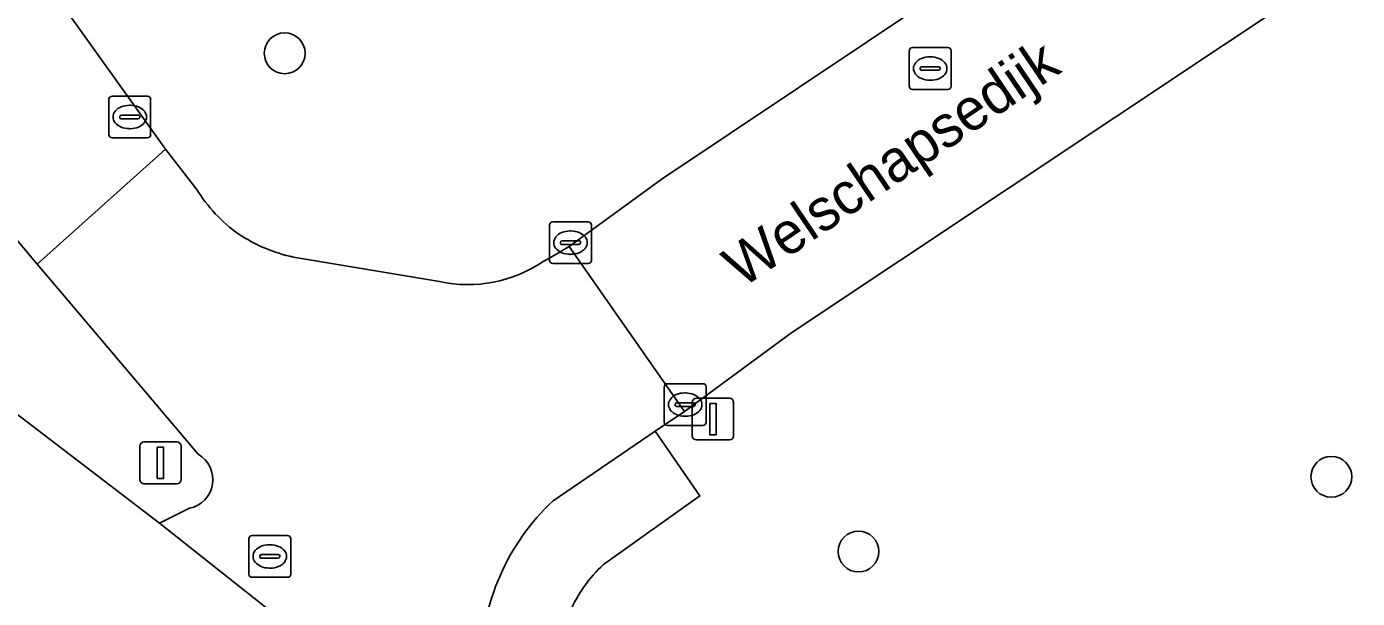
# Model space of a CAD drawing. Extents: x 157445 to 158888, y 383061 to 384688.
# Drawn here: x 157857.9 to 157889.8, y 383617.35 to 383631.04 of the extents above; entities that cross this region are included whole.
import ezdxf

# ---------------------------------------------------------------- set-up
doc = ezdxf.new("R2010")
doc.units = 0
for name, color, linetype in [('IMGEO_Boom', 7, 'Continuous'), ('IMGEO_Brandkraan', 7, 'Continuous'), ('IMGEO_Erf', 7, 'Continuous'), ('IMGEO_Fietspad_open', 7, 'Continuous'), ('IMGEO_Groenvoorziening', 7, 'Continuous'), ('IMGEO_Kolk', 7, 'Continuous'), ('IMGEO_Lichtmast', 7, 'Continuous'), ('IMGEO_Openbare_ruimte_label', 7, 'Continuous'), ('IMGEO_Rijbaan_lokaal_gesloten', 7, 'Continuous'), ('IMGEO_Rijbaan_lokaal_open', 7, 'Continuous'), ('IMGEO_Rioolput', 7, 'Continuous'), ('IMGEO_Verkeersbordpaal', 7, 'Continuous'), ('IMGEO_Voetpad_open', 7, 'Continuous')]:
    doc.layers.add(name, color=color, linetype=linetype)

msp = doc.modelspace()

# ---------------------------------------------------------------- linework, layer by layer
at = {"layer": 'IMGEO_Boom'}
for centre in [(157864.084, 383630.402), (157889.178, 383620.258), (157877.841, 383618.467)]:
    msp.add_circle(centre, 0.489, dxfattribs=at)
at = {"layer": 'IMGEO_Brandkraan'}
for p, q in [((157879.134, 383630.537), (157879.986, 383630.537)), ((157879.059, 383629.611), (157879.059, 383630.463)), ((157879.547, 383630.317), (157879.572, 383630.317)), ((157880.06, 383630.463), (157880.06, 383629.611)), ((157879.318, 383630.031), (157879.318, 383630.043)), ((157879.756, 383629.994), (157879.358, 383629.994)), ((157879.361, 383630.08), (157879.759, 383630.08)), ((157879.802, 383630.043), (157879.802, 383630.031)), ((157879.57, 383629.757), (157879.545, 383629.757)), ((157879.986, 383629.537), (157879.134, 383629.537))]:
    msp.add_line(p, q, dxfattribs=at)
for points in [[(157879.134, 383630.537), (157879.986, 383630.537)], [(157879.059, 383629.611), (157879.059, 383630.463)], [(157880.06, 383630.463), (157880.06, 383629.611)], [(157879.986, 383629.537), (157879.134, 383629.537)]]:
    msp.add_lwpolyline(points, dxfattribs=at)
for centre, radius, start, end in [((157879.136, 383630.461), 0.0765, 91.552, 178.448), ((157879.136, 383630.461), 0.0765, 91.552, 178.448), ((157879.984, 383630.461), 0.0765, 1.552, 88.448), ((157879.984, 383630.461), 0.0765, 1.552, 88.448), ((157879.358, 383630.04), 0.0403, 85.8775, 175.7526), ((157879.355, 383630.03), 0.0366, 178.938, 274.7102), ((157879.759, 383630.037), 0.043, 264.8664, 352.4533), ((157879.763, 383630.042), 0.0386, 1.7309, 96.639), ((157879.136, 383629.613), 0.0765, 181.552, 268.448), ((157879.136, 383629.613), 0.0765, 181.552, 268.448), ((157879.984, 383629.613), 0.0765, 271.552, 358.448), ((157879.984, 383629.613), 0.0765, 271.552, 358.448)]:
    msp.add_arc(centre, radius, start, end, dxfattribs=at)
for centre, major_axis, ratio, start_param, end_param in [((157879.546, 383630.037), (-0.387, 0.002), 0.722429, 4.712389, 7.853982), ((157879.571, 383630.037), (-0.39, 0.002), 0.717154, 1.570796, 4.712389)]:
    msp.add_ellipse(centre, major_axis=major_axis, ratio=ratio, start_param=start_param, end_param=end_param, dxfattribs=at)
at = {"layer": 'IMGEO_Erf'}
for points in [[(157898.785, 383680.85), (157847.632, 383646.169), (157853.571, 383638.788), (157861.226, 383628.104), (157861.967, 383627.151)], [(157870.28, 383625.415), (157870.471, 383625.516), (157870.906, 383625.776), (157873.135, 383627.394), (157904.332, 383648.231)], [(157864.294, 383625.52), (157867.796, 383624.934)]]:
    msp.add_lwpolyline(points, dxfattribs=at)
for centre, radius, start, end in [((157865.117, 383629.096), 3.702, 211.6974, 234.8047), ((157865.049, 383629.151), 3.708, 236.1489, 258.2581), ((157868.478, 383628.067), 3.206, 257.7179, 304.2003)]:
    msp.add_arc(centre, radius, start, end, dxfattribs=at)
at = {"layer": 'IMGEO_Fietspad_open'}
msp.add_lwpolyline([(157853.571, 383638.788), (157849.584, 383635.58), (157858.15, 383625.351), (157861.226, 383628.104)], close=True, dxfattribs=at)
at = {"layer": 'IMGEO_Groenvoorziening'}
for points in [[(157904.285, 383642.613), (157897.583, 383637.97), (157896.712, 383637.403), (157899.26, 383633.792), (157895.94, 383631.526), (157893.402, 383635.177), (157891.801, 383634.068), (157876.245, 383623.717), (157873.672, 383621.824), (157872.964, 383621.347), (157874.037, 383619.798), (157871.729, 383618.155)], [(157862.01, 383620.797), (157858.877, 383624.494), (157858.15, 383625.351), (157849.584, 383635.58)], [(157852.753, 383625.437), (157856.142, 383622.915), (157861.08, 383619.146), (157861.8, 383619.502)]]:
    msp.add_lwpolyline(points, dxfattribs=at)
for centre, radius, start, end in [((157861.663, 383620.189), 0.7, 281.3171, 60.2608), ((157873.934, 383615.734), 3.275, 132.3217, 156.9275)]:
    msp.add_arc(centre, radius, start, end, dxfattribs=at)
at = {"layer": 'IMGEO_Kolk'}
for p, q in [((157859.869, 383628.45), (157859.869, 383629.302)), ((157859.944, 383629.376), (157860.796, 383629.376)), ((157860.87, 383629.302), (157860.87, 383628.45)), ((157860.171, 383628.919), (157860.569, 383628.919)), ((157860.357, 383629.156), (157860.382, 383629.156)), ((157860.128, 383628.87), (157860.128, 383628.882)), ((157860.566, 383628.833), (157860.168, 383628.833)), ((157860.612, 383628.882), (157860.612, 383628.87)), ((157860.796, 383628.376), (157859.944, 383628.376)), ((157860.38, 383628.596), (157860.355, 383628.596)), ((157870.435, 383625.44), (157870.435, 383626.292)), ((157870.51, 383626.366), (157871.362, 383626.366)), ((157870.923, 383626.146), (157870.948, 383626.146)), ((157871.436, 383626.292), (157871.436, 383625.44)), ((157870.694, 383625.86), (157870.694, 383625.872)), ((157871.132, 383625.823), (157870.734, 383625.823)), ((157870.737, 383625.909), (157871.135, 383625.909)), ((157871.178, 383625.872), (157871.178, 383625.86)), ((157870.946, 383625.586), (157870.921, 383625.586)), ((157871.362, 383625.366), (157870.51, 383625.366)), ((157873.185, 383621.561), (157873.185, 383622.413)), ((157873.26, 383622.487), (157874.112, 383622.487)), ((157873.673, 383622.267), (157873.698, 383622.267)), ((157874.186, 383622.413), (157874.186, 383621.561)), ((157873.444, 383621.981), (157873.444, 383621.993)), ((157873.882, 383621.944), (157873.484, 383621.944)), ((157873.487, 383622.03), (157873.885, 383622.03)), ((157873.928, 383621.993), (157873.928, 383621.981)), ((157873.696, 383621.707), (157873.671, 383621.707)), ((157874.112, 383621.487), (157873.26, 383621.487))]:
    msp.add_line(p, q, dxfattribs=at)
for points in [[(157859.869, 383628.45), (157859.869, 383629.302)], [(157859.944, 383629.376), (157860.796, 383629.376)], [(157860.87, 383629.302), (157860.87, 383628.45)], [(157860.796, 383628.376), (157859.944, 383628.376)], [(157870.435, 383625.44), (157870.435, 383626.292)], [(157870.51, 383626.366), (157871.362, 383626.366)], [(157871.436, 383626.292), (157871.436, 383625.44)], [(157871.362, 383625.366), (157870.51, 383625.366)], [(157873.185, 383621.561), (157873.185, 383622.413)], [(157873.26, 383622.487), (157874.112, 383622.487)], [(157874.186, 383622.413), (157874.186, 383621.561)], [(157874.112, 383621.487), (157873.26, 383621.487)]]:
    msp.add_lwpolyline(points, dxfattribs=at)
for centre, radius, start, end in [((157859.946, 383629.3), 0.0765, 91.552, 178.448), ((157859.946, 383629.3), 0.0765, 91.552, 178.448), ((157860.794, 383629.3), 0.0765, 1.552, 88.448), ((157860.794, 383629.3), 0.0765, 1.552, 88.448), ((157860.168, 383628.879), 0.0403, 85.8775, 175.7526), ((157860.573, 383628.881), 0.0386, 1.7309, 96.639), ((157860.165, 383628.869), 0.0366, 178.938, 274.7102), ((157860.569, 383628.876), 0.043, 264.8664, 352.4533), ((157859.946, 383628.452), 0.0765, 181.552, 268.448), ((157859.946, 383628.452), 0.0765, 181.552, 268.448), ((157860.794, 383628.452), 0.0765, 271.552, 358.448), ((157860.794, 383628.452), 0.0765, 271.552, 358.448), ((157870.512, 383626.29), 0.0765, 91.552, 178.448), ((157870.512, 383626.29), 0.0765, 91.552, 178.448), ((157871.36, 383626.29), 0.0765, 1.552, 88.448), ((157871.36, 383626.29), 0.0765, 1.552, 88.448), ((157870.734, 383625.869), 0.0403, 85.8775, 175.7526), ((157870.731, 383625.859), 0.0366, 178.938, 274.7102), ((157871.135, 383625.866), 0.043, 264.8664, 352.4533), ((157871.139, 383625.871), 0.0386, 1.7309, 96.639), ((157870.512, 383625.442), 0.0765, 181.552, 268.448), ((157870.512, 383625.442), 0.0765, 181.552, 268.448), ((157871.36, 383625.442), 0.0765, 271.552, 358.448), ((157871.36, 383625.442), 0.0765, 271.552, 358.448), ((157873.262, 383622.411), 0.0765, 91.552, 178.448), ((157873.262, 383622.411), 0.0765, 91.552, 178.448), ((157874.11, 383622.411), 0.0765, 1.552, 88.448), ((157874.11, 383622.411), 0.0765, 1.552, 88.448), ((157873.484, 383621.99), 0.0403, 85.8775, 175.7526), ((157873.481, 383621.98), 0.0366, 178.938, 274.7102), ((157873.885, 383621.987), 0.043, 264.8664, 352.4533), ((157873.889, 383621.992), 0.0386, 1.7309, 96.639), ((157873.262, 383621.563), 0.0765, 181.552, 268.448), ((157873.262, 383621.563), 0.0765, 181.552, 268.448), ((157874.11, 383621.563), 0.0765, 271.552, 358.448), ((157874.11, 383621.563), 0.0765, 271.552, 358.448)]:
    msp.add_arc(centre, radius, start, end, dxfattribs=at)
for centre, major_axis, ratio, start_param, end_param in [((157860.356, 383628.876), (-0.387, 0.002), 0.722429, 4.712389, 7.853982), ((157860.381, 383628.876), (-0.39, 0.002), 0.717154, 1.570796, 4.712389), ((157870.922, 383625.866), (-0.387, 0.002), 0.722429, 4.712389, 7.853982), ((157870.947, 383625.866), (-0.39, 0.002), 0.717154, 1.570796, 4.712389), ((157873.672, 383621.987), (-0.387, 0.002), 0.722429, 4.712389, 7.853982), ((157873.697, 383621.987), (-0.39, 0.002), 0.717154, 1.570796, 4.712389)]:
    msp.add_ellipse(centre, major_axis=major_axis, ratio=ratio, start_param=start_param, end_param=end_param, dxfattribs=at)
at = {"layer": 'IMGEO_Lichtmast'}
for p, q in [((157873.856, 383621.239), (157873.856, 383622.039)), ((157873.856, 383622.039), (157873.856, 383621.239)), ((157873.956, 383622.139), (157874.746, 383622.139)), ((157874.746, 383622.139), (157873.956, 383622.139)), ((157874.846, 383622.039), (157874.846, 383621.239)), ((157874.846, 383621.239), (157874.846, 383622.039)), ((157874.746, 383621.139), (157873.956, 383621.139)), ((157873.956, 383621.139), (157874.746, 383621.139))]:
    msp.add_line(p, q, dxfattribs=at)
msp.add_lwpolyline([(157874.276, 383622.014), (157874.426, 383622.014), (157874.426, 383621.264), (157874.276, 383621.264), (157874.276, 383622.014)], dxfattribs=at)
for centre, start, end in [((157873.956, 383622.039), 90, 180), ((157873.956, 383622.039), 90, 180), ((157874.746, 383622.039), 0, 90), ((157874.746, 383622.039), 360, 90), ((157873.956, 383621.239), 180, 270), ((157873.956, 383621.239), 180, 270), ((157874.746, 383621.239), 270, 0), ((157874.746, 383621.239), 270, 0)]:
    msp.add_arc(centre, 0.1, start, end, dxfattribs=at)
at = {"layer": 'IMGEO_Rijbaan_lokaal_gesloten'}
msp.add_lwpolyline([(157881.641, 383602.379), (157870.429, 383611.742), (157861.08, 383619.146), (157856.142, 383622.915), (157852.589, 383618.202), (157856.906, 383614.859), (157858.634, 383613.533)], dxfattribs=at)
at = {"layer": 'IMGEO_Rijbaan_lokaal_open'}
for points in [[(157904.332, 383648.231), (157873.135, 383627.394), (157870.906, 383625.776), (157873.672, 383621.824), (157876.245, 383623.717), (157891.801, 383634.068), (157893.402, 383635.177), (157896.712, 383637.403), (157897.583, 383637.97), (157904.285, 383642.613)], [(157861.967, 383627.151), (157861.226, 383628.104), (157858.15, 383625.351), (157858.877, 383624.494), (157862.01, 383620.797)], [(157870.517, 383619.684), (157872.964, 383621.347), (157873.672, 383621.824), (157870.906, 383625.776), (157870.471, 383625.516), (157870.28, 383625.415)], [(157867.796, 383624.934), (157864.294, 383625.52)], [(157861.8, 383619.502), (157861.08, 383619.146), (157870.429, 383611.742)]]:
    msp.add_lwpolyline(points, dxfattribs=at)
for centre, radius, start, end in [((157865.117, 383629.096), 3.702, 211.6974, 234.8047), ((157865.049, 383629.151), 3.708, 236.1489, 258.2581), ((157868.478, 383628.067), 3.206, 257.7179, 304.2003), ((157861.663, 383620.189), 0.7, 281.3171, 60.2608), ((157874.287, 383615.671), 5.506, 133.2084, 225.5219)]:
    msp.add_arc(centre, radius, start, end, dxfattribs=at)
at = {"layer": 'IMGEO_Rioolput'}
for p, q in [((157863.226, 383617.924), (157863.226, 383618.776)), ((157863.301, 383618.85), (157864.153, 383618.85)), ((157864.227, 383618.776), (157864.227, 383617.924)), ((157863.528, 383618.393), (157863.926, 383618.393)), ((157863.714, 383618.63), (157863.739, 383618.63)), ((157863.485, 383618.344), (157863.485, 383618.356)), ((157863.923, 383618.307), (157863.525, 383618.307)), ((157863.969, 383618.356), (157863.969, 383618.344)), ((157864.153, 383617.85), (157863.301, 383617.85)), ((157863.737, 383618.07), (157863.712, 383618.07))]:
    msp.add_line(p, q, dxfattribs=at)
for points in [[(157863.226, 383617.924), (157863.226, 383618.776)], [(157863.301, 383618.85), (157864.153, 383618.85)], [(157864.227, 383618.776), (157864.227, 383617.924)], [(157864.153, 383617.85), (157863.301, 383617.85)]]:
    msp.add_lwpolyline(points, dxfattribs=at)
for centre, radius, start, end in [((157863.303, 383618.774), 0.0765, 91.552, 178.448), ((157863.303, 383618.774), 0.0765, 91.552, 178.448), ((157864.151, 383618.774), 0.0765, 1.552, 88.448), ((157864.151, 383618.774), 0.0765, 1.552, 88.448), ((157863.525, 383618.353), 0.0403, 85.8775, 175.7526), ((157863.93, 383618.355), 0.0386, 1.7309, 96.639), ((157863.522, 383618.343), 0.0366, 178.938, 274.7102), ((157863.926, 383618.35), 0.043, 264.8664, 352.4533), ((157863.303, 383617.926), 0.0765, 181.552, 268.448), ((157863.303, 383617.926), 0.0765, 181.552, 268.448), ((157864.151, 383617.926), 0.0765, 271.552, 358.448), ((157864.151, 383617.926), 0.0765, 271.552, 358.448)]:
    msp.add_arc(centre, radius, start, end, dxfattribs=at)
for centre, major_axis, ratio, start_param, end_param in [((157863.713, 383618.35), (-0.387, 0.002), 0.722429, 4.712389, 7.853982), ((157863.738, 383618.35), (-0.39, 0.002), 0.717154, 1.570796, 4.712389)]:
    msp.add_ellipse(centre, major_axis=major_axis, ratio=ratio, start_param=start_param, end_param=end_param, dxfattribs=at)
at = {"layer": 'IMGEO_Verkeersbordpaal'}
for p, q in [((157860.61, 383620.192), (157860.61, 383620.992)), ((157860.61, 383620.992), (157860.61, 383620.192)), ((157860.71, 383621.092), (157861.5, 383621.092)), ((157861.5, 383621.092), (157860.71, 383621.092)), ((157861.6, 383620.992), (157861.6, 383620.192)), ((157861.6, 383620.192), (157861.6, 383620.992)), ((157861.5, 383620.092), (157860.71, 383620.092)), ((157860.71, 383620.092), (157861.5, 383620.092))]:
    msp.add_line(p, q, dxfattribs=at)
msp.add_lwpolyline([(157861.03, 383620.967), (157861.18, 383620.967), (157861.18, 383620.217), (157861.03, 383620.217), (157861.03, 383620.967)], dxfattribs=at)
for centre, start, end in [((157860.71, 383620.992), 90, 180), ((157860.71, 383620.992), 90, 180), ((157861.5, 383620.992), 0, 90), ((157861.5, 383620.992), 360, 90), ((157860.71, 383620.192), 180, 270), ((157860.71, 383620.192), 180, 270), ((157861.5, 383620.192), 270, 0), ((157861.5, 383620.192), 270, 0)]:
    msp.add_arc(centre, 0.1, start, end, dxfattribs=at)
at = {"layer": 'IMGEO_Voetpad_open'}
msp.add_lwpolyline([(157871.729, 383618.155), (157874.037, 383619.798), (157872.964, 383621.347), (157870.517, 383619.684)], dxfattribs=at)
for centre, radius, start, end in [((157874.287, 383615.671), 5.506, 133.2084, 225.5219), ((157873.934, 383615.734), 3.275, 132.3217, 156.9275)]:
    msp.add_arc(centre, radius, start, end, dxfattribs=at)

# ---------------------------------------------------------------- texts
at = {"layer": 'IMGEO_Openbare_ruimte_label'}
msp.add_text('Welschapsedijk', height=1, rotation=34.0716, dxfattribs=at).set_placement((157875.048, 383624.761))

doc.saveas('drawing.dxf')
